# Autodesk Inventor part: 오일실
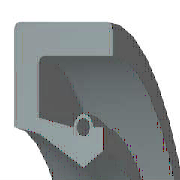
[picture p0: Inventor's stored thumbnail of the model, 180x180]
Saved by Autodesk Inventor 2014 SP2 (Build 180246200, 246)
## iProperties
IsCustomPart: 1
Company: 한국ATC센터
Created: 2014-10
Part Number: 오일실
Material: 고무
Description: 오일-실
Document SubType Name: Modeling
Standard: KS B 2804
Designer: 한국ATC센터
Standards Organization: KS
Language: ko-KR
Size Designation: S - 25 40 8
Categories: <MemberInstance><Categories><Category DisplayName="샤프트 부품" InternalName="7f7aeb1f-a693-4053-b835-cee3144e0d98" Mnemonic="SHFT"><Category DisplayName="실링" Intern
Density: 0.93 g/cm^3
Mass: 2.48215 g
Surface Area: 40.3381 cm^2
Volume: 2.66898 cm^3
Appearance: 고무 - 검은색 - 버전 1.1
Author: KYOUNG IL JANG
Revision Number: 1
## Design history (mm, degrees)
revolve "본체" stored, may be unused: angle "d17" = 90 deg
revolve "스프링1" stored, may be unused: angle "d18" = 90 deg
body "Solid1"
sketch "스케치1"
  geometry: L1 (0, 20)-(8, 20); L2 (8, 20)-(8, 18.75); L3 (8, 18.75)-(1.75, 18.75); L4 (0, 20)-(0, 14.6); L5 (0, 14.6)-(1.75, 14.25); L6 (1.75, 14.25)-(4.9, 12.5); L7 (4.9, 12.5)-(0, 12.5); L8 (6.3, 13.375)-(6.3, 14.6); L9 (0, 0)-(9.586, 0) reference; L10 (4.9, 12.5)-(6.3, 13.375); L11 (0, 18)-(0, -3) reference; L12 (-1.917, 0)-(11.503, 0) reference; L13 (4.2, 14.6)-(1.75, 15.09); L14 (1.75, 15.09)-(1.75, 18.75); L15 (6.3, 14.6)-(5.6, 14.6); C1 r 0.455 at (4.9, 14.6); A1 r 0.7 centre (4.9, 14.6) between (5.6, 14.6) and (4.2, 14.6)
  constraints: 26 end point, 5 horizontal alignment, 4 perpendicular, 2 centre point, 2 collinear, 2 horizontal, 2 parallel, 2 point on circle, 2 point on line, 2 vertical alignment, 1 coincident
  dimensions: "d0" = 40 diameter of L1 L9 (= SD2); "d1" = 26.75 diameter of L8.start L9 (= ABDM); "d2" = 1.25 distance of L1.end L2.end (computed from SD); "d3" = 0.91 diameter of C1 (= SPDI); "d4" = 1.4 diameter of A1 (= SPDA); "d5" = 25 diameter of L6.end L9 (= NND); "d6" = 28.5 diameter of L5.end L9 (= TKDM); "d7" = 29.2 diameter of L4.end L9 (= HLDM); "d8" = 4.9 distance from line of C1.centre L4 (= SPDST); "d9" = 6.3 distance between parallel lines of L8 L4 (= SDI); "d10" = 8 distance between parallel lines of L2 L4 (= SWDT); "d12" = 1.75 distance between parallel lines of L14 L4 (= SD)
fillet "모깎기1" dims "d11" = 0.3 (= RR)
other parameters: "SD2" = 40 [user parameter; used in 1 equation term], "SWDT" = 8 [user parameter; used in 1 equation term], "RR" = 0.3 [user parameter; used in 1 equation term], "SD" = 1.75 [user parameter; used in 2 equation terms], "NND" = 25 [user parameter; used in 1 equation term], "SPDA" = 1.4 [user parameter; used in 1 equation term], "SPDI" = 0.91 [user parameter; used in 1 equation term], "TKDM" = 28.5 [user parameter; used in 1 equation term], "HLDM" = 29.2 [user parameter; used in 1 equation term], "ABDM" = 26.75 [user parameter; used in 1 equation term], "SDI" = 6.3 [user parameter; used in 1 equation term], "SPDST" = 4.9 [user parameter; used in 1 equation term], "d13" = 0, "d14" = 0, "d15" = 0, "LAB" = 0.35 [user parameter]
